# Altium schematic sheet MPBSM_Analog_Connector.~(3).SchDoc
size 431 x 279 mm; Date: Not shown in title block; ApprovedBy: Not shown in title block; CheckedBy: Not shown in title block; Author: Not shown in title block; CompanyName: Not shown in title block; Engineer: Not shown in title block; Organization: Not shown in title block; Address1: Not shown in title block; Address2: Not shown in title block; Address3: Not shown in title block; Address4: Not shown in title block; DocumentNumber: 1; Revision: Use project parameter SCH_Rev; SheetNumber: 2; SheetTotal: 3; PageSetup: Record=PageOptions¦CenterHorizontal=True¦CenterVertical=True¦PrintScale=1.00¦XCorrection=1.00¦YCorrection=1.00¦PrintKind=0¦BorderSize=5000000¦LeftOffset=0¦BottomOffset=0¦Orientation=2¦PaperLength=1000¦PaperWidth=1000¦Scale=100¦PaperSource=15¦PrintQuality=600¦MediaType=1¦DitherType=10¦PaperKind=Letter¦PrintScaleMode=1
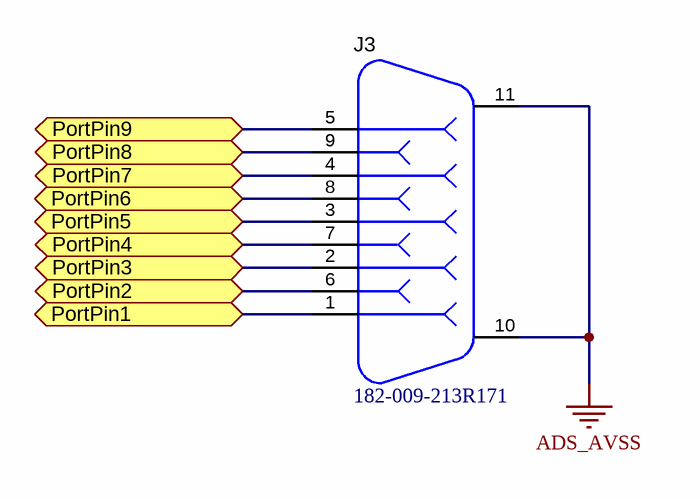
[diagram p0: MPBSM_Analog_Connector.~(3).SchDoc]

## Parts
J3  182-009-213R171  [NORCOMP_182-009-213R171]

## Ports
PortPin1 (bidir), PortPin2 (bidir), PortPin3 (bidir), PortPin4 (bidir), PortPin5 (bidir), PortPin6 (bidir), PortPin7 (bidir), PortPin8 (bidir), PortPin9 (bidir)

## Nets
ADS_AVSS: J3.10 J3.11
PortPin1: J3.1 ; port PortPin1
PortPin2: J3.6 ; port PortPin2
PortPin3: J3.2 ; port PortPin3
PortPin4: J3.7 ; port PortPin4
PortPin5: J3.3 ; port PortPin5
PortPin6: J3.8 ; port PortPin6
PortPin7: J3.4 ; port PortPin7
PortPin8: J3.9 ; port PortPin8
PortPin9: J3.5 ; port PortPin9

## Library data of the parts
J3 = 182-009-213R171: CONN DB9 FEMALE R/A SOLDER TH; Manufacturer: NorComp; SymbolCreator: a0412235; CompType: Connector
